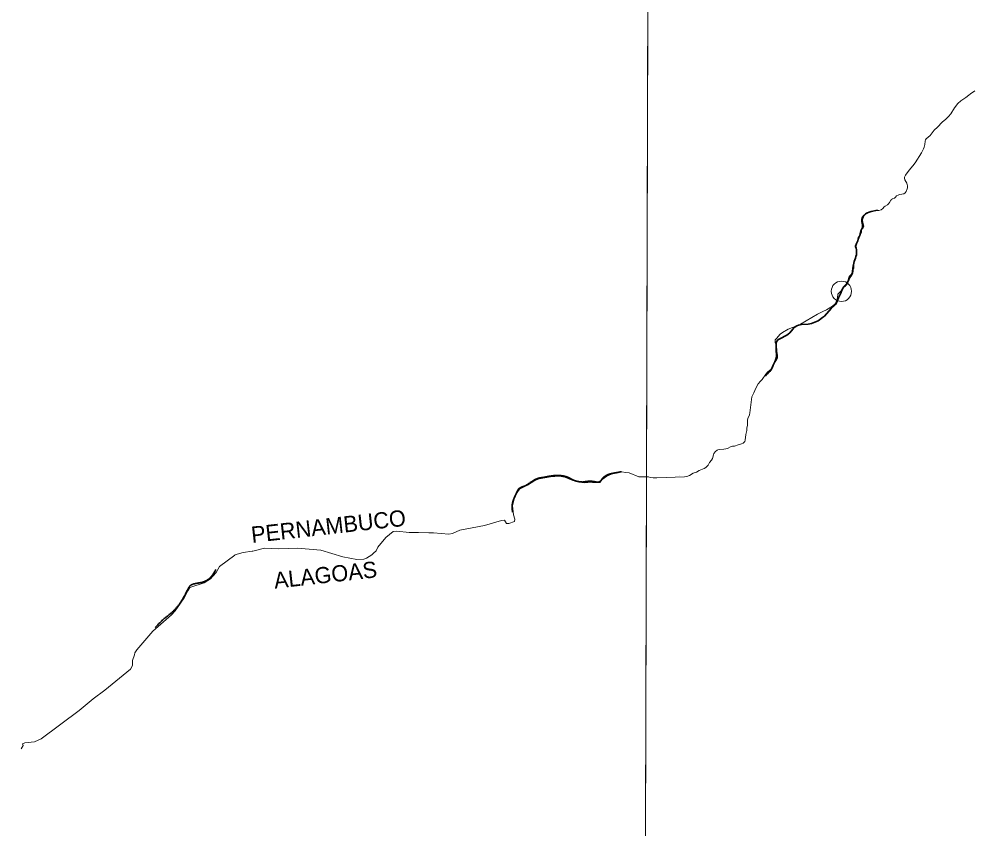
# Model space of a CAD drawing. Extents: x 553962 to 842807, y 8883888 to 9032388.
# Drawn here: x 582541 to 587242, y 8915855 to 8919850 of the extents above; entities that cross this region are included whole.
import ezdxf
from ezdxf.enums import TextEntityAlignment as Align

# ---------------------------------------------------------------- set-up
doc = ezdxf.new("R2010")
doc.units = 0
doc.header["$LTSCALE"] = 200
doc.header["$PDMODE"] = 32
doc.header["$PDSIZE"] = 100
doc.linetypes.add('LONG_DASH_SHORT_DASH', pattern=[9.9, 6, -1.2, 1.5, -1.2])
doc.layers.add('6', color=7, linetype='Continuous', lineweight=13)

msp = doc.modelspace()

# ---------------------------------------------------------------- linework, layer by layer
at = {"layer": '6', "linetype": 'LONG_DASH_SHORT_DASH', "lineweight": 35}
msp.add_line((585799, 8917597.9), (585799.3, 8917597.8), dxfattribs=at)
at = {"layer": '6'}
for points in [[(585656.3, 8924738.8), (585614.8, 8909969.8), (585573.6, 8896026.7)], [(586916.9, 8918999.4), (586921.8, 8919011.7), (586923.2, 8919017.8), (586923.8, 8919027.8), (586919.9, 8919040.7), (586909.9, 8919057.1), (586909, 8919064.2), (586909.4, 8919069.7), (586914.4, 8919080.4), (586932.4, 8919104.2), (586949.8, 8919125.1), (586961.5, 8919140.2), (586992.8, 8919190.2), (587002.7, 8919209.4), (587006.2, 8919218.4), (587008.9, 8919230.4), (587010.4, 8919247.4), (587012.9, 8919254.6), (587016, 8919258.6), (587035, 8919274.8), (587055.6, 8919302.4), (587072, 8919316.4), (587094, 8919340.4), (587112.3, 8919355.2), (587126.1, 8919368.8), (587137.1, 8919382), (587155.1, 8919411), (587172.6, 8919433.8), (587187.4, 8919446.2), (587211.4, 8919462), (587226.2, 8919474.8), (587234.8, 8919481.4), (587256, 8919495)], [(586679.6, 8918760.5), (586680.3, 8918772.5), (586692.5, 8918786.5), (586696.8, 8918798.9), (586696.9, 8918809.3), (586697.7, 8918812.7), (586699.3, 8918815.3), (586704.2, 8918820.1), (586707.7, 8918826.9), (586707.4, 8918834.5), (586702.6, 8918847.7), (586701.8, 8918857.5), (586703.1, 8918864.1), (586709.7, 8918881.3), (586721, 8918893.5), (586725.9, 8918895.7), (586766.1, 8918904.9), (586782.2, 8918905.1), (586794.3, 8918909.1), (586801.8, 8918914.7), (586808.8, 8918923.3), (586813, 8918927.3), (586824.3, 8918933.9), (586830.1, 8918938.5), (586834.8, 8918944.1), (586841.9, 8918955.9), (586845.8, 8918960.3), (586848.8, 8918962.4), (586859.7, 8918966.8), (586863.7, 8918970.4), (586869.3, 8918977.4), (586877.2, 8918981.7), (586883.6, 8918984.1), (586895.7, 8918985.2), (586905.7, 8918987.4), (586911.9, 8918992.7), (586916.9, 8918999.4)], [(586136.8, 8917879.9), (586143.9, 8917898.3), (586146.5, 8917907.1), (586150.7, 8917947.5), (586156.3, 8917986.5), (586166.2, 8918006.3), (586175.4, 8918028.7), (586186.6, 8918050.1), (586197.8, 8918063.5), (586206.1, 8918071.9), (586225, 8918098.7), (586234.8, 8918109.9), (586249.5, 8918120.5), (586256.8, 8918127.7), (586261.3, 8918135.7), (586262.8, 8918149.5), (586276.3, 8918165.5), (586281.8, 8918176.7), (586282.8, 8918182.3), (586282.8, 8918191.1), (586279.2, 8918209.5), (586279.1, 8918219.3), (586275.1, 8918241.3), (586270.8, 8918255.1), (586270.6, 8918261.3), (586271.5, 8918267.7), (586278.2, 8918274.1), (586295.8, 8918294.9), (586307.4, 8918303.7), (586335.1, 8918320.1), (586377.8, 8918336.7), (586395.1, 8918344.9), (586480.1, 8918393.5), (586505.7, 8918406.7), (586524.1, 8918414.9), (586554, 8918433.1), (586568.4, 8918447.3), (586570.6, 8918451.1), (586575.7, 8918463.9), (586578.3, 8918475.3), (586579.7, 8918491.9), (586595.5, 8918507.3), (586602.8, 8918522.3), (586607.5, 8918529.5), (586619.7, 8918540.1), (586627.3, 8918548.9), (586630.1, 8918555.5), (586632.3, 8918569.5), (586634.1, 8918575.1), (586636.7, 8918579.5), (586645.9, 8918589.1), (586648.8, 8918594.9), (586650.6, 8918604.3), (586653.5, 8918631.7), (586658.1, 8918644.7), (586665.3, 8918659.3), (586672.6, 8918692.7), (586672.6, 8918710.3), (586671.1, 8918715.7), (586665.9, 8918726.3), (586666, 8918731.5), (586668, 8918736.7), (586678.5, 8918755.1), (586678.5, 8918755.1), (586679.6, 8918760.5)], [(585824.4, 8917592.5), (585835.6, 8917593.5), (585848.5, 8917598.3), (585866.6, 8917609.5), (585883, 8917614.7), (585896.8, 8917622.9), (585921, 8917633.3), (585928.7, 8917638.5), (585940.3, 8917649.7), (585947.5, 8917662.7), (585957.1, 8917673.5), (585961.2, 8917682.5), (585965.9, 8917699.7), (585968.9, 8917706.9), (585976, 8917717.1), (585984.1, 8917723.9), (585988.6, 8917725.7), (585994.5, 8917727.1), (586017.6, 8917728.5), (586028.1, 8917729.9), (586035.3, 8917731.9), (586054, 8917741.3), (586060.6, 8917742.5), (586070, 8917742.7), (586088.9, 8917750.3), (586104.1, 8917754.3), (586112.5, 8917757.7), (586118, 8917762.1), (586120.7, 8917766.5), (586122.9, 8917773.1), (586126.9, 8917800.7), (586130.7, 8917821.1), (586131.4, 8917832.3), (586133.7, 8917846.3), (586134.3, 8917870.5), (586136.8, 8917879.9)], [(585406.5, 8917564.6), (585417.5, 8917578), (585441.3, 8917595.2), (585463.8, 8917604.5), (585514.8, 8917615.6), (585533.1, 8917613.4)], [(585533.1, 8917613.4), (585551.5, 8917611.2), (585597.6, 8917591.8)], [(584946, 8917362.1), (584956.7, 8917362.1), (584984.5, 8917371.3), (584987.1, 8917382.3), (584980.7, 8917404.5), (584974.8, 8917448.6), (584983.7, 8917481.7), (584998.1, 8917514.8), (585010.1, 8917531), (585049.8, 8917550.4), (585085.7, 8917573.9), (585106.9, 8917582), (585162.1, 8917591.8), (585206.3, 8917594.7), (585224.1, 8917592.2)], [(585224.1, 8917592.2), (585233.4, 8917590.9), (585273.5, 8917573.1), (585302.3, 8917565), (585331.2, 8917562.9), (585406.5, 8917564.6)], [(585597.6, 8917591.8), (585645.8, 8917591.3), (585655.1, 8917588.7), (585668.4, 8917587.5), (585687.5, 8917587.3), (585824.4, 8917592.5)], [(584562.5, 8917316.2), (584584.8, 8917316), (584661, 8917309.7), (584679.6, 8917312.2), (584715.2, 8917328.8), (584836.7, 8917352.1), (584920.8, 8917375.9), (584935.7, 8917377.6), (584946, 8917362.1)], [(584289.7, 8917215.3), (584302.2, 8917227.5), (584311.2, 8917245.5), (584349.8, 8917291.8), (584386.3, 8917322.1), (584405.1, 8917324.1), (584466.3, 8917316.9), (584511.8, 8917316.6), (584562.5, 8917316.2)], [(583694.7, 8917225.9), (583751.3, 8917239.9), (583784.8, 8917238.2)], [(583784.8, 8917238.2), (583823, 8917236.2), (583913.9, 8917240), (584030.3, 8917229.4), (584139.1, 8917197.5), (584207.1, 8917184.8), (584241.1, 8917186), (584254.7, 8917190.7), (584281.9, 8917207.8), (584289.7, 8917215.3)], [(583497.2, 8917101.5), (583513.7, 8917119.7), (583530.7, 8917150.3), (583605.6, 8917205.9)], [(583605.6, 8917205.9), (583606.2, 8917206.4), (583647.1, 8917217.9), (583691.7, 8917225.1), (583694.7, 8917225.9)], [(583374.4, 8917029.3), (583384.1, 8917046.7), (583454.1, 8917069.1), (583484.8, 8917087.9), (583497.2, 8917101.5)], [(583110.2, 8916714.5), (583112.9, 8916723.3), (583122.7, 8916738.7), (583200.6, 8916830.8), (583293.7, 8916911.2), (583311.9, 8916931.1), (583355.3, 8916994.9), (583374.4, 8917029.3)], [(583090.8, 8916642.8), (583100.4, 8916661.6), (583101.2, 8916686.4), (583110.2, 8916714.5)], [(582550.9, 8916251), (582561.6, 8916267.1), (582557.7, 8916274.2), (582569.7, 8916279), (582618.1, 8916284.9), (582650.7, 8916300), (582838.2, 8916439.2), (582906.1, 8916497.3), (582963.8, 8916539.2), (583090.8, 8916642.8)]]:
    msp.add_lwpolyline(points, dxfattribs=at)
msp.add_lwpolyline([(585645.8, 8921027.3), (574684.9, 8921064.7), (574653.9, 8910009.3), (585614.8, 8909969.8)], close=True, dxfattribs=at)
at = {"layer": '6', "linetype": 'LONG_DASH_SHORT_DASH', "lineweight": 35}
for points in [[(586698.2, 8918860.5), (586699.5, 8918868.4), (586701.6, 8918872.3), (586709.1, 8918881.7), (586716.2, 8918889), (586725.8, 8918894.1), (586735.2, 8918897.5), (586743.7, 8918899.7), (586775.5, 8918907)], [(586597.6, 8918506.7), (586605.9, 8918523.4), (586611.9, 8918529.9), (586617.3, 8918534), (586622.3, 8918538.9), (586623.4, 8918540.9), (586626.4, 8918548.8), (586631.3, 8918557.1), (586634.3, 8918565.1), (586637.8, 8918573), (586643.9, 8918581.7), (586648.8, 8918589.4), (586652.3, 8918595.6), (586654.7, 8918605.5), (586654.8, 8918613.8), (586656.7, 8918622.1), (586657.8, 8918638.2), (586659.7, 8918646.3), (586661, 8918654.2), (586663.5, 8918662.4), (586666.6, 8918670.9), (586668.9, 8918678.8), (586672.1, 8918687.1), (586672.3, 8918702.8), (586672, 8918712), (586671, 8918719.4), (586667.1, 8918727.6), (586666.9, 8918728.6), (586672.8, 8918742), (586679.1, 8918756), (586680.9, 8918764.7), (586683.4, 8918772.6), (586688.5, 8918781.8), (586690.3, 8918790.4), (586695.8, 8918807.9), (586701.3, 8918821.4), (586701.6, 8918825.4), (586701.4, 8918834.4), (586699.1, 8918851.1), (586698.2, 8918860.5)], [(586513.5, 8918384.7), (586547.2, 8918421.3), (586562.5, 8918435.2), (586568.8, 8918442), (586573.9, 8918450.3), (586577.2, 8918457.8), (586580, 8918465.9), (586583.2, 8918474), (586594.1, 8918498), (586597.6, 8918506.7)], [(586222.6, 8918087.9), (586223.9, 8918090.1), (586228.4, 8918096.1), (586236.5, 8918103.6), (586243.8, 8918110.9), (586250.2, 8918118.5), (586254.6, 8918126.4), (586260.8, 8918142.7), (586268.8, 8918158.2), (586272.8, 8918166.7), (586277.2, 8918183.1), (586278.1, 8918191.2), (586277.5, 8918199.5), (586276, 8918207.8), (586276, 8918223.7), (586276.6, 8918240), (586275.8, 8918254), (586276.7, 8918256.6), (586280.2, 8918263.9), (586287.4, 8918268.9), (586293.9, 8918272.7), (586327.8, 8918291.2), (586334.7, 8918295.4), (586343.5, 8918302.7), (586357.8, 8918319.5), (586363.1, 8918326.4), (586369.2, 8918332), (586377.3, 8918336.3), (586385.6, 8918339.6), (586393.6, 8918341.5), (586401.5, 8918342.9), (586433.8, 8918344.2), (586442.3, 8918345.8), (586450.6, 8918348.2), (586466.5, 8918353.8), (586474.8, 8918357.3), (586483.3, 8918361.6), (586490.3, 8918366.2), (586504.2, 8918377.5), (586513.5, 8918384.7)]]:
    msp.add_lwpolyline(points, dxfattribs=at)
for points in [[(585320.8, 8917565.9), (585379.6, 8917568.1), (585403.9, 8917567.3), (585406.1, 8917568.8), (585417.5, 8917582.4), (585451.2, 8917604.6), (585489.2, 8917612.5), (585512.1, 8917617.4)], [(584975.9, 8917417.5), (584975.5, 8917419.7), (584973.4, 8917450.5), (584981.3, 8917482.8), (584997.8, 8917518.6), (585007.8, 8917534.4), (585031.4, 8917545.1), (585065.1, 8917565.2), (585093, 8917581.7), (585131, 8917589.6), (585175.4, 8917597.4), (585208.4, 8917598.2), (585232.7, 8917594.6), (585252.1, 8917588.1), (585282.1, 8917573.1), (585320.8, 8917565.9)], [(583212.7, 8916848.6), (583254.2, 8916889.7), (583303.2, 8916930.2), (583370.6, 8917031.5), (583385.8, 8917055.2), (583431.4, 8917068.7), (583482, 8917092.3), (583511.3, 8917134.2)]]:
    msp.add_spline(points, degree=3, dxfattribs=at)
at = {"layer": '6'}
msp.add_point((586597.6, 8918506.7), dxfattribs=at)

# ---------------------------------------------------------------- texts
for s, p in [('PERNAMBUCO', (584071.7, 8917308.3)), ('ALAGOAS', (584056.6, 8917068.5))]:
    msp.add_text(s, height=80, rotation=6.379, dxfattribs=at).set_placement(p, align=Align.CENTER)

doc.saveas('drawing.dxf')
